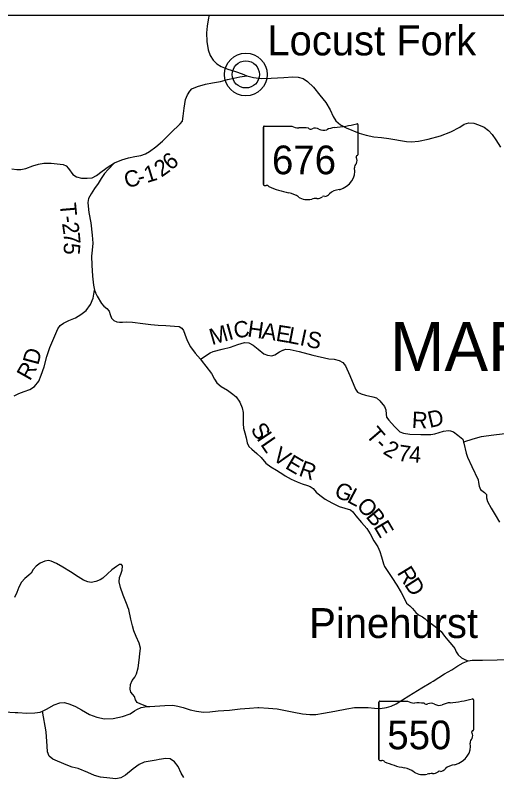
# Model space of a CAD drawing. Extents: x -84548 to 2262448, y -162180 to 525962.
# Drawn here: x 92440 to 101301, y 156669 to 170686 of the extents above; entities that cross this region are included whole.
import ezdxf

# ---------------------------------------------------------------- set-up
doc = ezdxf.new("R2010")
doc.units = 0
for name, color, linetype in [('GM_P_US_Location', 7, 'Continuous'), ('GM_X_Adjacent_County_Text', 7, 'Continuous'), ('GM_X_County', 7, 'Continuous'), ('GM_X_County_Road', 7, 'Continuous'), ('GM_X_Major_Lake_Text', 7, 'Continuous'), ('GM_X_Major_River', 7, 'Continuous'), ('GM_X_Minor_Lake', 7, 'Continuous'), ('GM_X_Minor_River_Text', 7, 'Continuous'), ('GM_X_Rail_Line', 7, 'Continuous'), ('GM_X_Township_Road', 7, 'Continuous'), ('GM_X_Township_Road_Text', 7, 'Continuous')]:
    doc.layers.add(name, color=color, linetype=linetype)

msp = doc.modelspace()

# ---------------------------------------------------------------- linework, layer by layer
at = {"layer": 'GM_X_County'}
msp.add_line((77085, 170686), (110973, 170686), dxfattribs=at)
at = {"layer": 'GM_X_Major_Lake_Text'}
for points in [[(96006, 170686), (95994, 170638), (95969, 170487), (95962, 170361), (95968, 170201), (95989, 170048), (96026, 169945), (96083, 169859), (96151, 169789), (96232, 169744), (96354, 169695), (96495, 169652), (96619, 169607), (96701, 169570), (96824, 169537), (96970, 169524), (97152, 169530), (97384, 169538), (97549, 169551), (97649, 169544), (97740, 169519), (97820, 169463), (97927, 169362), (98048, 169215), (98154, 169078), (98233, 168944), (98288, 168822), (98340, 168741), (98427, 168671), (98532, 168612), (98772, 168514), (98895, 168479), (99039, 168450), (99181, 168435), (99313, 168415), (99640, 168363), (99732, 168356), (99860, 168367), (100037, 168403), (100265, 168469), (100458, 168541), (100623, 168626), (100703, 168683), (100788, 168704), (100881, 168699), (100963, 168669), (101067, 168626), (101152, 168563), (101218, 168493), (101287, 168392), (101372, 168258)], [(100089, 158406), (100090, 158406), (100131, 158430), (100342, 158563), (100473, 158640), (100587, 158711), (100682, 158764), (100776, 158801), (100850, 158813), (100879, 158814)], [(100879, 158814), (100881, 158814), (101038, 158815), (101307, 158823), (101580, 158833), (101838, 158841), (102040, 158849), (102395, 158856), (102707, 158864), (102963, 158870), (103205, 158876), (103291, 158872), (103393, 158855), (103528, 158818), (103642, 158779), (103763, 158724), (103839, 158698), (103925, 158683), (104009, 158686), (104093, 158698), (104219, 158733), (104244, 158741)], [(96906, 157942), (96924, 157944), (97102, 157931), (97262, 157917), (97414, 157886), (97567, 157857), (97727, 157828), (97863, 157812), (97971, 157815), (98113, 157840), (98320, 157878), (98542, 157920), (98682, 157941), (98814, 157946), (98934, 157943), (99050, 157932), (99158, 157925), (99270, 157942), (99361, 157971), (99449, 158012), (99686, 158160), (99922, 158306), (100089, 158406)], [(92484, 157850), (92487, 157849), (92656, 157841), (92802, 157844), (92900, 157861), (92939, 157878), (93018, 157913), (93155, 157992), (93259, 158031), (93345, 158038), (93445, 158008), (93547, 157965), (93659, 157898), (93808, 157816), (93942, 157763), (94082, 157736), (94242, 157743), (94414, 157778), (94555, 157827), (94633, 157880), (94677, 157904), (94760, 157941), (94862, 157962), (94915, 157965)], [(94915, 157965), (94915, 157965), (95010, 157971), (95190, 157983), (95340, 157984), (95434, 157969), (95530, 157945), (95658, 157901), (95777, 157875), (95903, 157861), (96023, 157866), (96173, 157881), (96380, 157895), (96578, 157917), (96754, 157930), (96906, 157942)], [(92241, 157866), (92441, 157852), (92484, 157850)]]:
    msp.add_lwpolyline(points, dxfattribs=at)
at = {"layer": 'GM_X_Major_River'}
for radius in [393, 249]:
    msp.add_circle((96684, 169596), radius, dxfattribs=at)
at = {"layer": 'GM_X_Minor_Lake'}
for points in [[(92423, 163680), (92509, 163724), (92603, 163759), (92709, 163795), (92794, 163852), (92872, 163950), (92919, 164059), (92974, 164217), (93023, 164406), (93078, 164572), (93153, 164743), (93223, 164914), (93268, 164974), (93326, 165020), (93428, 165065), (93549, 165119), (93647, 165176), (93745, 165252), (93822, 165361), (93873, 165477), (93897, 165624)], [(97369, 164519), (97416, 164538), (97502, 164534), (97662, 164495), (97916, 164430), (98210, 164359), (98308, 164355), (98399, 164332), (98469, 164292), (98517, 164232), (98596, 164054), (98701, 163806), (98741, 163750), (98805, 163715), (98888, 163693), (99020, 163663), (99090, 163646), (99152, 163590), (99234, 163486), (99257, 163424), (99265, 163340), (99275, 163286), (99316, 163232), (99420, 163118), (99515, 163020), (99587, 162995), (99699, 162977), (99907, 162966), (100089, 162967), (100164, 162981), (100240, 163006), (100322, 163032), (100414, 163045), (100450, 163034), (100450, 163034)], [(95880, 164313), (95950, 164225), (96053, 164093), (96106, 163987), (96150, 163919), (96228, 163851), (96347, 163782), (96447, 163714), (96507, 163660), (96574, 163564), (96616, 163458), (96634, 163374), (96633, 163266), (96634, 163166), (96642, 163088), (96666, 163000), (96687, 162910), (96709, 162813), (96740, 162750), (96794, 162696), (96888, 162618), (96965, 162546), (97051, 162444), (97143, 162375), (97246, 162311), (97380, 162224), (97380, 162224)], [(100450, 163034), (100506, 163017), (100588, 162957), (100677, 162881), (100692, 162827), (100697, 162807), (100736, 162623), (100764, 162551), (100843, 162379), (100960, 162137), (100965, 162083), (100975, 162015), (101005, 161959), (101074, 161904), (101110, 161862), (101110, 161804), (101132, 161736), (101199, 161614), (101272, 161488), (101354, 161358)], [(97380, 162224), (97406, 162208), (97518, 162144), (97631, 162096), (97723, 162061), (97817, 162033), (97867, 162013), (97921, 161975), (97979, 161910), (98046, 161850), (98144, 161778), (98266, 161711), (98402, 161645), (98507, 161612), (98609, 161580), (98651, 161546), (98707, 161470), (98814, 161352), (98912, 161241), (98973, 161143), (99041, 161009), (99110, 160901), (99152, 160815), (99183, 160715), (99216, 160591), (99238, 160541), (99284, 160465), (99373, 160339), (99461, 160193), (99542, 160058), (99615, 159920), (99639, 159864), (99703, 159814), (99752, 159768), (99814, 159694), (99862, 159648), (99932, 159611), (99986, 159575), (100029, 159531), (100097, 159487), (100195, 159417), (100276, 159340), (100338, 159254), (100398, 159182), (100475, 159098), (100529, 159032), (100553, 158968), (100594, 158912), (100650, 158858), (100728, 158823)], [(94515, 159793), (94515, 159793), (94502, 159826), (94427, 160010), (94379, 160150), (94352, 160256), (94356, 160337), (94385, 160401), (94409, 160471), (94415, 160551), (94394, 160575), (94360, 160573), (94305, 160541), (94215, 160476), (94135, 160402), (94054, 160323), (94000, 160291), (93924, 160261), (93840, 160244), (93774, 160254), (93696, 160288), (93596, 160349), (93456, 160443), (93317, 160528), (93201, 160596), (93103, 160640), (93051, 160651), (92985, 160639), (92897, 160599), (92827, 160546), (92768, 160484), (92734, 160417), (92692, 160379), (92619, 160319), (92555, 160248), (92508, 160160), (92468, 160058), (92425, 159969)], [(94862, 157962), (94754, 158006), (94684, 158038), (94655, 158086), (94633, 158146), (94605, 158182), (94567, 158226), (94552, 158282), (94560, 158366), (94590, 158438), (94641, 158505), (94669, 158563), (94700, 158675), (94721, 158818), (94735, 158930), (94744, 159034), (94718, 159126), (94667, 159252), (94621, 159356), (94600, 159444), (94570, 159572), (94533, 159746), (94515, 159793)], [(100728, 158823), (100776, 158801)], [(95089, 156984), (95035, 156976), (94815, 156937), (94718, 156896), (94610, 156814), (94471, 156699), (94381, 156648), (94293, 156632), (94179, 156641), (94007, 156661), (93901, 156692), (93775, 156746), (93595, 156821), (93487, 156847), (93376, 156890), (93132, 156991), (93064, 157051), (93035, 157125), (93027, 157233), (93011, 157494), (92939, 157878)], [(95540, 156654), (95496, 156736), (95437, 156859), (95369, 156945), (95289, 156999), (95209, 157003), (95090, 156984), (95089, 156984)]]:
    msp.add_lwpolyline(points, dxfattribs=at)
at = {"layer": 'GM_X_Minor_River_Text'}
msp.add_lwpolyline([(92378, 167859), (92468, 167845), (92544, 167846), (92632, 167866), (92764, 167915), (92867, 167945), (92969, 167964), (93101, 167964), (93323, 167937), (93379, 167912), (93417, 167864), (93500, 167756), (93566, 167710), (93660, 167684), (93762, 167687), (93854, 167695), (93938, 167736), (94041, 167814), (94147, 167895), (94264, 167966), (94400, 168026), (94524, 168063), (94642, 168084), (94753, 168104), (94837, 168132), (94911, 168175), (95026, 168264), (95148, 168370), (95305, 168523), (95472, 168686), (95516, 168739), (95531, 168827), (95547, 168973), (95572, 169136), (95607, 169220), (95651, 169286), (95691, 169334), (95792, 169371), (95940, 169414), (96072, 169440), (96220, 169469), (96346, 169502), (96463, 169530), (96571, 169553), (96701, 169570)], dxfattribs=at)
at = {"layer": 'GM_X_Rail_Line'}
for p, q in [((97006, 168627), (97006, 167571)), ((97006, 167571), (97006, 168627)), ((97006, 167571), (97006, 168627)), ((97023, 168645), (97533, 168645)), ((98746, 168672), (98746, 168119)), ((98746, 168119), (98746, 168119)), ((99134, 158042), (99134, 156986)), ((99134, 156986), (99134, 158042)), ((99134, 156986), (99134, 158042)), ((99151, 158061), (99660, 158061)), ((100874, 158087), (100874, 157534)), ((100874, 157534), (100874, 157534))]:
    msp.add_line(p, q, dxfattribs=at)
for centre, major_axis, start_param, end_param in [((97026, 168629), (20.2, 0), 1.712693, 3.28349), ((97654, 168768), (196, 0), 4.042523, 4.731795), ((98126, 170086), (1845, 0), 4.814394, 5.042369), ((98727, 168674), (19.4, 0), 6.141152, 7.989035), ((97719, 168052), (702, 0), 1.404758, 1.657858), ((97878, 168635), (56.4, 0), 3.836095, 5.185415), ((97961, 168513), (117, 0), 0.950623, 2.079405), ((98112, 168680), (141, 0), 4.081561, 5.145723), ((98362, 168323), (371, 0), 1.699011, 2.107814), ((98742, 168078), (30, 0), 1.883978, 3.671073), ((98551, 168008), (180, 0), 5.934695, 6.695948), ((98725, 168117), (20.7, 0), 5.05454, 6.418171), ((98815, 167888), (131, 0), 2.387724, 3.262537), ((98230, 167817), (462, 0), 5.101752, 6.440018), ((97026, 167568), (20.3, 0), 3.00124, 4.508301), ((97029, 167676), (155, 0), 4.665946, 4.897461), ((97061, 167510), (56, 0), 0.519207, 1.627899), ((97767, 168459), (1333, 0), 4.195997, 4.488961), ((97370, 167096), (417, 0), 0.823519, 1.323587), ((98104, 167468), (149, 0), 4.937069, 5.64225), ((98424, 167274), (253, 0), 1.647645, 2.488434), ((97821, 167504), (265, 0), 4.026481, 4.996735), ((97974, 167139), (217, 0), 1.495662, 1.94098), ((97993, 167425), (141, 0), 4.691044, 5.507374), ((98121, 167323), (39.7, 0), 1.147584, 2.315152), ((99154, 158045), (20.2, 0), 1.712693, 3.28349), ((99782, 158183), (196, 0), 4.042523, 4.731795), ((99847, 157467), (702, 0), 1.404758, 1.657858), ((100006, 158050), (56.4, 0), 3.836095, 5.185415), ((100089, 157928), (117, 0), 0.950623, 2.079405), ((100240, 158096), (141, 0), 4.081561, 5.145723), ((100489, 157738), (371, 0), 1.699011, 2.107814), ((100254, 159501), (1845, 0), 4.814394, 5.042369), ((100855, 158089), (19.4, 0), 6.141152, 7.989035), ((100869, 157494), (30, 0), 1.883978, 3.671073), ((100679, 157424), (180, 0), 5.934695, 6.695948), ((100853, 157532), (20.7, 0), 5.05454, 6.418171), ((100357, 157232), (462, 0), 5.101752, 6.440018), ((100943, 157303), (131, 0), 2.387724, 3.262537), ((99154, 156984), (20.3, 0), 3.00124, 4.508301), ((99157, 157092), (155, 0), 4.665946, 4.897461), ((99189, 156925), (56, 0), 0.519207, 1.627899), ((99895, 157874), (1333, 0), 4.195997, 4.488961), ((100552, 156689), (253, 0), 1.647645, 2.488434), ((99498, 156511), (417, 0), 0.823519, 1.323587), ((99949, 156920), (265, 0), 4.026481, 4.996735), ((100102, 156554), (217, 0), 1.495662, 1.94098), ((100121, 156841), (141, 0), 4.691044, 5.507374), ((100249, 156738), (39.7, 0), 1.147584, 2.315152), ((100232, 156883), (149, 0), 4.937069, 5.64225)]:
    msp.add_ellipse(centre, major_axis=major_axis, ratio=0.8, start_param=start_param, end_param=end_param, dxfattribs=at)
at = {"layer": 'GM_X_Township_Road_Text'}
for points in [[(94264, 167966), (94153, 167847), (94083, 167774), (94022, 167682), (93969, 167586), (93901, 167499), (93836, 167401), (93790, 167312), (93776, 167240), (93779, 167172), (93797, 167054), (93828, 166862), (93855, 166637), (93866, 166489), (93855, 166363), (93841, 166253), (93850, 166088), (93861, 165882), (93880, 165716), (93897, 165624), (93917, 165580), (93918, 165578)], [(93918, 165578), (93949, 165512), (94026, 165382), (94072, 165332), (94124, 165288), (94166, 165236), (94187, 165178), (94213, 165110), (94253, 165068), (94311, 165045), (94357, 165039), (94411, 165039), (94479, 165043), (94595, 165036), (94791, 165011), (94937, 164993), (95071, 164982), (95213, 164975), (95373, 164965), (95457, 164954), (95505, 164926), (95535, 164884), (95558, 164814), (95602, 164698), (95663, 164584), (95749, 164464), (95848, 164354), (95880, 164314), (95880, 164313)], [(95848, 164354), (96027, 164471), (96085, 164498), (96251, 164540), (96404, 164577), (96534, 164624), (96658, 164664), (96738, 164657), (96818, 164613), (96912, 164537), (97013, 164452), (97085, 164426), (97165, 164416), (97217, 164437), (97304, 164493), (97367, 164518), (97369, 164519)], [(101840, 163010), (101783, 163020), (101659, 163012), (101503, 162989), (101246, 162958), (101013, 162927), (100860, 162881), (100692, 162827)]]:
    msp.add_lwpolyline(points, dxfattribs=at)

# ---------------------------------------------------------------- texts
at = {"layer": 'GM_P_US_Location'}
msp.add_text('MARIETTA', height=900, rotation=0, dxfattribs=at).set_placement((99337, 164138))
at = {"layer": 'GM_X_Adjacent_County_Text'}
for s, p in [('Locust Fork', (97080, 169947)), ('Pinehurst', (97850, 159223))]:
    msp.add_text(s, height=550, rotation=0, dxfattribs=at).set_placement(p)
at = {"layer": 'GM_X_County_Road'}
for s, rotation, p in [('6', 39.5945, (95301, 167817)), ('2', 35.2275, (95130, 167695)), ('C', 13.7674, (94483, 167501)), ('1', 17.018, (94860, 167595)), ('-', 14.1041, (94724, 167561))]:
    msp.add_text(s, height=300, rotation=rotation, dxfattribs=at).set_placement(p)
at = {"layer": 'GM_X_Rail_Line'}
for s, p in [('676', (97165, 167759)), ('550', (99287, 157175))]:
    msp.add_text(s, height=528, dxfattribs=at).set_placement(p)
at = {"layer": 'GM_X_Township_Road'}
for s, rotation, p in [('T', 275.1496, (93258, 167222)), ('-', 278.586, (93281, 166979)), ('2', 278.4087, (93299, 166857)), ('7', 275.279, (93326, 166679)), ('5', 265.1179, (93343, 166509)), ('M', 16.1198, (96061, 164611)), ('I', 15.8939, (96374, 164701)), ('C', 9.6445, (96484, 164733)), ('H', 351.6929, (96702, 164774)), ('A', 351.1365, (96963, 164736)), ('E', 350.6955, (97223, 164695)), ('L', 349.07, (97442, 164659)), ('I', 347.8458, (97661, 164617)), ('S', 347.5117, (97781, 164591)), ('D', 75.0587, (92862, 164233)), ('R', 60.5485, (92710, 163943)), ('R', 357.0481, (99733, 163093)), ('D', 13.0852, (100068, 163088)), ('S', 303.4331, (96760, 163064)), ('I', 303.4542, (96872, 162895)), ('T', 310.3661, (98878, 162953)), ('L', 304.465, (96943, 162787)), ('V', 325.6014, (97155, 162517)), ('-', 314.4953, (99040, 162764)), ('2', 329.1339, (99191, 162625)), ('7', 351.9207, (99472, 162487)), ('4', 356.4574, (99681, 162459)), ('E', 329.4073, (97391, 162356)), ('R', 340.2827, (97641, 162216)), ('G', 337.9733, (98292, 161831)), ('L', 332.1622, (98529, 161735)), ('O', 311.9385, (98705, 161647)), ('B', 309.2084, (98879, 161454)), ('E', 300.5566, (99028, 161273)), ('R', 301.5712, (99458, 160426)), ('D', 302.9187, (99591, 160209))]:
    msp.add_text(s, height=300, rotation=rotation, dxfattribs=at).set_placement(p)

doc.saveas('drawing.dxf')
